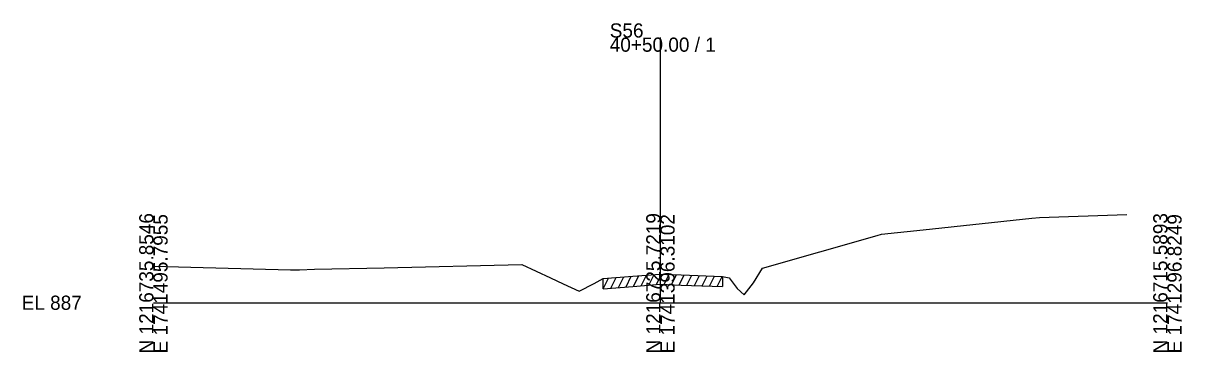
# Model space of a CAD drawing. Extents: x -26 to 1203, y -10 to 19541.
# Drawn here: x -25.7 to 202.8, y 15490.3 to 15555.2 of the extents above; entities that cross this region are included whole.
import ezdxf

# ---------------------------------------------------------------- set-up
doc = ezdxf.new("R2010")
doc.units = 0
for name, color, linetype in [('RD_GPK_XS_Cell', 7, 'Continuous'), ('RD_XS_ExGround', 7, 'Continuous'), ('RD_XS_ExPaveRet', 7, 'Continuous'), ('RD_XS_TX_Elev_EX', 7, 'Continuous')]:
    doc.layers.add(name, color=color, linetype=linetype)

msp = doc.modelspace()

# ---------------------------------------------------------------- linework, layer by layer
at = {"layer": 'RD_GPK_XS_Cell'}
for p, q in [((100, 15500), (100, 15552.33)), ((0, 15500), (100, 15500)), ((100, 15500), (200, 15500))]:
    msp.add_line(p, q, dxfattribs=at)
at = {"layer": 'RD_XS_ExGround'}
msp.add_lwpolyline([(0, 15507.19), (27.02, 15506.5), (28.83, 15506.48), (31.8, 15506.64), (45.5, 15506.91), (72.69, 15507.56), (78.31, 15504.92), (80.83, 15503.73), (83.96, 15502.25), (86.93, 15503.77), (87.52, 15504.11), (88.71, 15504.77), (94.56, 15505.23), (99.97, 15505.66), (104.06, 15505.49), (112.26, 15505.18), (113.56, 15504.94), (115.12, 15502.8), (116.51, 15501.56), (118.34, 15503.91), (120.15, 15506.83), (142.73, 15513.29), (143.61, 15513.52), (151.8, 15514.41), (173.28, 15516.71), (174.75, 15516.82), (191.97, 15517.44)], dxfattribs=at)
at = {"layer": 'RD_XS_ExPaveRet'}
for p, q in [((88.71, 15502.77), (89.75, 15504.85)), ((88.71, 15502.77), (88.71, 15504.77)), ((90.21, 15502.89), (91.25, 15504.97)), ((91.71, 15503.01), (92.75, 15505.09)), ((93.21, 15503.12), (94.25, 15505.21)), ((94.56, 15503.23), (99.97, 15503.66)), ((94.71, 15503.24), (95.75, 15505.33)), ((96.21, 15503.36), (97.25, 15505.44)), ((97.71, 15503.48), (98.75, 15505.56)), ((99.21, 15503.6), (100.24, 15505.65)), ((99.97, 15503.66), (104.06, 15503.49)), ((100.71, 15503.63), (101.69, 15505.59)), ((102.21, 15503.57), (103.19, 15505.53)), ((103.71, 15503.51), (104.69, 15505.47)), ((105.21, 15503.45), (106.19, 15505.41)), ((106.71, 15503.39), (107.69, 15505.35)), ((108.21, 15503.33), (109.19, 15505.3)), ((109.71, 15503.28), (110.69, 15505.24)), ((111.21, 15503.22), (112.19, 15505.18)), ((112.26, 15505.18), (112.26, 15503.18)), ((88.71, 15502.77), (94.56, 15503.23)), ((104.06, 15503.49), (112.26, 15503.18))]:
    msp.add_line(p, q, dxfattribs=at)

# ---------------------------------------------------------------- texts
at = {"layer": 'RD_GPK_XS_Cell'}
for s, p in [('S56', (90, 15552.33)), ('40+50.00 / 1', (90, 15549.53)), ('EL 887', (-26, 15498.6))]:
    msp.add_text(s, height=2.8, dxfattribs=at).set_placement(p)
for s, p in [('N 1216735.8546', (0, 15490)), ('N 1216725.7219', (100, 15490)), ('N 1216715.5893', (200, 15490)), ('E 1741495.7955', (2.8, 15490)), ('E 1741396.3102', (102.8, 15490)), ('E 1741296.8249', (202.8, 15490))]:
    msp.add_text(s, height=2.8, rotation=90, dxfattribs=at).set_placement(p)
at = {"layer": 'RD_XS_TX_Elev_EX'}
msp.add_text('889.83', height=0.1, rotation=90, dxfattribs=at).set_placement((100.1, 15505.66))

doc.saveas('drawing.dxf')
